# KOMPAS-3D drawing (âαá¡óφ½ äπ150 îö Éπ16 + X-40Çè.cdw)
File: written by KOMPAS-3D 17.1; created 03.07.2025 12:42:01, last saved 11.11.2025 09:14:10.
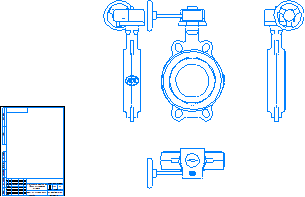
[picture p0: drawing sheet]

Sheet 1: A4, portrait

Title block, sheet 1: name: Гранвэл Ду150 МФ Ру16 + / X-40АК (Габаритный / чертёж); material: Сталь 20  ГОСТ 1050-88; mass: 10,21; sheets: 1; organisation: ООО "Торговый дом АДЛ"; sheet format: A4; stored path: \\adlc.lan\data\АДЛ_ПКД\3D-модели\ADL production\Дисковые поворотные затворы ГРАНВЭЛ\межфланцевый с китайским редуктором Ру16\KOMPAS 2D\Гранвэл Ду150 МФ Ру16 + X-40АК.cdw

Views: Вид 1, Спереди, Проекционный вид 2, Проекционный вид 3, Проекционный вид 4
Referenced files in \\adlc.lan\data\АДЛ_ПКД\3D-модели\ADL production\Дисковые поворотные затворы ГРАНВЭЛ\межфланцевый с китайским редуктором Ру16\KOMPAS 3D\: Гранвэл Ду150 МФ Ру16 + X-40АК.m3d
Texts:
  Andrey
  АДЛ
Dimensions and other numbers on the sheet: 1:1; 1; 10,21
